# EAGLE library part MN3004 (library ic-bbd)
512-Stage Lo Noise BBD
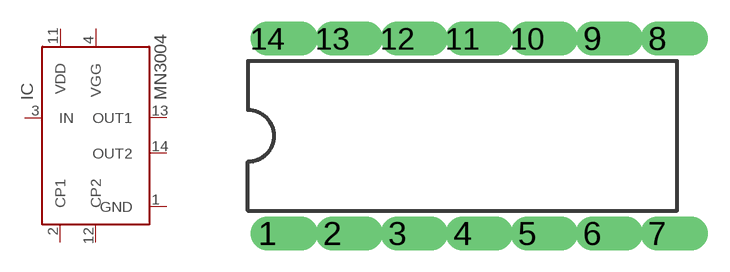
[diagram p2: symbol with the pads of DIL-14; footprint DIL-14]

Designator prefix IC

## MN3004  [DIL-14]
1  GND
2  CP1
3  IN
4  VGG
11  VDD
12  CP2
13  OUT1
14  OUT2

## Footprint DIL-14 (pad centres in mm)
Dual In Line Package
drill 0.813 offset: 1 -7.62,-3.81; 2 -5.08,-3.81; 3 -2.54,-3.81; 4 0,-3.81; 5 2.54,-3.81; 6 5.08,-3.81; 7 7.62,-3.81; 8 7.62,3.81; 9 5.08,3.81; 10 2.54,3.81; 11 0,3.81; 12 -2.54,3.81; 13 -5.08,3.81; 14 -7.62,3.81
